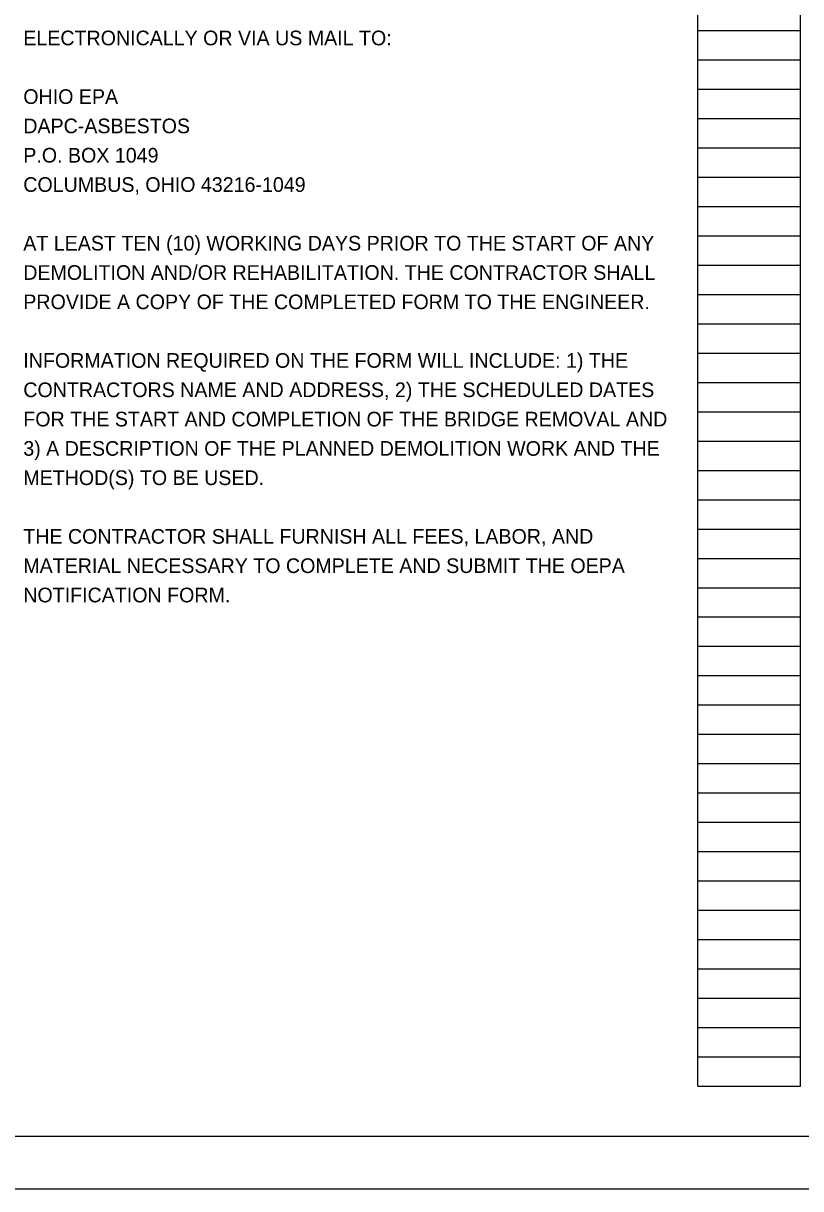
# Model space of a CAD drawing. Extents: x 0 to 84.3, y -13.4 to 22.
# Drawn here: x 17.24 to 24.66, y 0 to 11.13 of the extents above; entities that cross this region are included whole.
import ezdxf

# ---------------------------------------------------------------- set-up
doc = ezdxf.new("R2010")
doc.units = 0
for name, color, linetype in [('SH_Border', 7, 'Continuous'), ('SH_Cut_Line', 7, 'Continuous'), ('SH_Data', 7, 'Continuous'), ('SH_Text', 7, 'Continuous')]:
    doc.layers.add(name, color=color, linetype=linetype)

msp = doc.modelspace()

# ---------------------------------------------------------------- linework, layer by layer
at = {"layer": 'SH_Border'}
msp.add_lwpolyline([(1.5, 21.5), (33.5, 21.5), (33.5, 0.5), (1.5, 0.5)], close=True, dxfattribs=at)
at = {"layer": 'SH_Cut_Line'}
msp.add_lwpolyline([(0, 0), (34, 0), (34, 22), (0, 22)], close=True, dxfattribs=at)
at = {"layer": 'SH_Data'}
for p, q in [((23.68, 0.98), (23.68, 21.14)), ((24.66, 0.98), (24.66, 21.14)), ((23.68, 11.06), (24.66, 11.06)), ((23.68, 10.78), (24.66, 10.78)), ((23.68, 10.5), (24.66, 10.5)), ((23.68, 10.22), (24.66, 10.22)), ((23.68, 9.94), (24.66, 9.94)), ((23.68, 9.66), (24.66, 9.66)), ((23.68, 9.38), (24.66, 9.38)), ((23.68, 9.1), (24.66, 9.1)), ((23.68, 8.82), (24.66, 8.82)), ((23.68, 8.54), (24.66, 8.54)), ((23.68, 8.26), (24.66, 8.26)), ((23.68, 7.98), (24.66, 7.98)), ((23.68, 7.7), (24.66, 7.7)), ((23.68, 7.42), (24.66, 7.42)), ((23.68, 7.14), (24.66, 7.14)), ((23.68, 6.86), (24.66, 6.86)), ((23.68, 6.58), (24.66, 6.58)), ((23.68, 6.3), (24.66, 6.3)), ((23.68, 6.02), (24.66, 6.02)), ((23.68, 5.74), (24.66, 5.74)), ((23.68, 5.46), (24.66, 5.46)), ((23.68, 5.18), (24.66, 5.18)), ((23.68, 4.9), (24.66, 4.9)), ((23.68, 4.62), (24.66, 4.62)), ((23.68, 4.34), (24.66, 4.34)), ((23.68, 4.06), (24.66, 4.06)), ((23.68, 3.78), (24.66, 3.78)), ((23.68, 3.5), (24.66, 3.5)), ((23.68, 3.22), (24.66, 3.22)), ((23.68, 2.94), (24.66, 2.94)), ((23.68, 2.66), (24.66, 2.66)), ((23.68, 2.38), (24.66, 2.38)), ((23.68, 2.1), (24.66, 2.1)), ((23.68, 1.82), (24.66, 1.82)), ((23.68, 1.54), (24.66, 1.54)), ((23.68, 1.26), (24.66, 1.26)), ((23.68, 0.98), (24.66, 0.98))]:
    msp.add_line(p, q, dxfattribs=at)

# ---------------------------------------------------------------- texts
at = {"layer": 'SH_Text'}
for s, p in [('ELECTRONICALLY OR VIA US MAIL TO:', (17.24, 10.92)), ('OHIO EPA', (17.24, 10.36)), ('DAPC-ASBESTOS', (17.24, 10.08)), ('P.O. BOX 1049', (17.24, 9.8)), ('COLUMBUS, OHIO 43216-1049', (17.24, 9.52)), ('AT LEAST TEN (10) WORKING DAYS PRIOR TO THE START OF ANY', (17.24, 8.96)), ('DEMOLITION AND/OR REHABILITATION. THE CONTRACTOR SHALL', (17.24, 8.68)), ('PROVIDE A COPY OF THE COMPLETED FORM TO THE ENGINEER.', (17.24, 8.4)), ('INFORMATION REQUIRED ON THE FORM WILL INCLUDE: 1) THE', (17.24, 7.84)), ('CONTRACTORS NAME AND ADDRESS, 2) THE SCHEDULED DATES', (17.24, 7.56)), ('FOR THE START AND COMPLETION OF THE BRIDGE REMOVAL AND', (17.24, 7.28)), ('3) A DESCRIPTION OF THE PLANNED DEMOLITION WORK AND THE', (17.24, 7)), ('METHOD(S) TO BE USED.', (17.24, 6.72)), ('THE CONTRACTOR SHALL FURNISH ALL FEES, LABOR, AND', (17.24, 6.16)), ('MATERIAL NECESSARY TO COMPLETE AND SUBMIT THE OEPA', (17.24, 5.88)), ('NOTIFICATION FORM.', (17.24, 5.6))]:
    msp.add_text(s, height=0.14, dxfattribs=at).set_placement(p)

doc.saveas('drawing.dxf')
